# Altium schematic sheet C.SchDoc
size A2
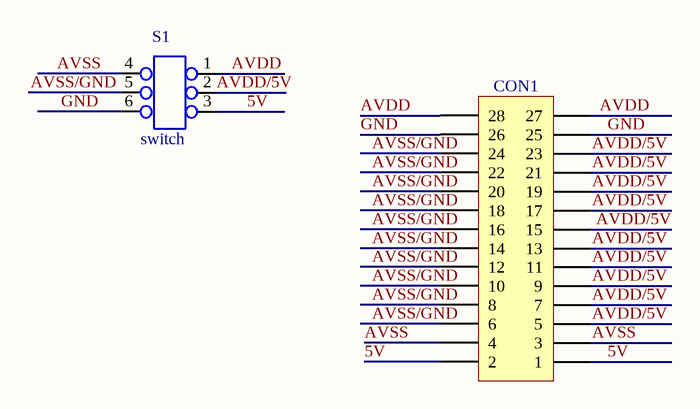
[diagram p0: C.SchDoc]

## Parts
CON1  SV1  [26]  (value not drawn)
S1  switch  [switch1]

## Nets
5V: CON1.1 CON1.2 S1.3
AVDD: CON1.27 CON1.28 S1.1
AVDD/5V: CON1.5 CON1.7 CON1.9 CON1.11 CON1.13 CON1.15 CON1.17 CON1.19 CON1.21 CON1.23 S1.2
AVSS: CON1.3 CON1.4 S1.4
AVSS/GND: CON1.6 CON1.8 CON1.10 CON1.12 CON1.14 CON1.16 CON1.18 CON1.20 CON1.22 CON1.24 S1.5
GND: CON1.25 CON1.26 S1.6

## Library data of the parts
CON1 = 26
S1 = switch 1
